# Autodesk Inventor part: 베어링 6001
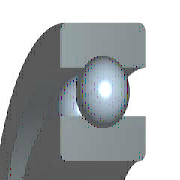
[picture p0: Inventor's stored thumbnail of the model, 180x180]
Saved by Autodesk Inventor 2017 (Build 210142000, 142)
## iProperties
Created: 2012-02
Part Number: 베어링 6001
Material: 강철, 연강
Description: 깊은 그루브 볼 베어링
Document SubType Name: Modeling
Standard: KS B 2023
Designer: mduedu
Standards Organization: KS
Language: ko-KR
Size Designation: 6001 - 12 x 28 x 8
Categories: <MemberInstance><Categories><Category DisplayName="샤프트 부품" InternalName="7f7aeb1f-a693-4053-b835-cee3144e0d98" Mnemonic="SHFT"><Category DisplayName="베어링" Inter
Density: 7.86 g/cm^3
Mass: 21.4854 g
Surface Area: 31.1809 cm^2
Volume: 2.73351 cm^3
Appearance: 노란색
IsCustomPart: 1
Author: mduedu
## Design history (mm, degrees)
sketch "스케치" dims "d0" = 4.16 (= -0.26 x WD + 0.26 x BD)
  geometry: L1 (1.92, 10)-(6.08, 10); L2 (4, 10)-(4, 7.92); L3 (4, 10)-(4, 12.08); L4 (2.454, 8.608)-(0, 8.608); L5 (0, 6)-(8, 6); L6 (2.454, 11.392)-(0, 11.392); L7 (0, 14)-(8, 14); L8 (8, 6)-(8, 8.608); L9 (5.546, 8.608)-(8, 8.608); L10 (5.546, 11.392)-(8, 11.392); L11 (8, 14)-(8, 11.392); L12 (-1.4, 0)-(8.4, 0) reference; L13 (0, -0.3)-(0, 5.3) reference
  constraints: 22 end point, 4 point on line, 2 collinear, 2 perpendicular, 2 symmetric about line, 1 midpoint, 1 parallel, 14 other
  dimensions: "d9" = 12 diameter of L5 L12 (= WD); "d11" = 28 diameter of L7 L12 (= BD); "d12" = 8 distance between parallel lines of L8 L13 (= KB); "d13" = 17.216 diameter of L9 L12 (= 0.326 x BD + 0.674 x WD)
revolve "본체" stored, may be unused: angle "d6" = 90 deg
revolve "볼" stored, may be unused: angle "d7" = 90 deg
pattern_circular "IDS_ARRAYBALL[SIMPL:T]" dims angle "d3" = 360 deg
body "Solid1"
fillet "모깎기1" dims "d1" = 0.3 (= KRS)
other parameters: "WD" = 12 [user parameter; used in 5 equation terms], "BD" = 28 [user parameter; used in 5 equation terms], "KB" = 8 [user parameter; used in 1 equation term], "KRS" = 0.3 [user parameter; used in 1 equation term], "d4" = 0, "d5" = 0, "d8" = 0, "d14" = 0, "d15" = 0, "BBA" = 0 [user parameter], "BC0" = 2360000 [user parameter], "BC" = 5070000 [user parameter], "BR" = 14 (= 0.5 x BD) [user parameter], "WR" = 6 (= 0.5 x WD) [user parameter]
